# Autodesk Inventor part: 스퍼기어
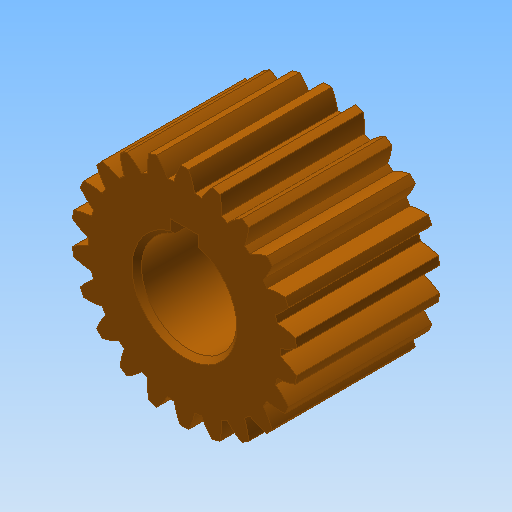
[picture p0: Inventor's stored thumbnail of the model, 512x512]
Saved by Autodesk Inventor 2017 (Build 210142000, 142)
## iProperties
Created: 2019-03
Part Number: 스퍼기어
Material: 강철
Document SubType Name: Modeling
Designer: mduedu
Categories: <?xml version="1.0" encoding="UTF-16"?> <MemberInstance><Categories><FamilyTemplate><FamilyTemplateParameter ValueType="xs:double" Id="1" ObjectReferenceKey="da
Density: 1 g/cm^3
Appearance: 주황색
CustomPartVersion: 1
Author: mduedu
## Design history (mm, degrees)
sketch "Sketch1"
  geometry: C1 r 23.6 at (0, 0)
  constraints: 1 centre point
  dimensions: "d0" = 47.2 diameter of C1 (= da_da)
extrude "Extrusion1" new body sketch "Sketch1" distance "d1" = 30 (= da_b); taper "d2" = 0 deg
workplane "Work Plane2"
sketch "Sketch2"
  geometry: C1 r 23.6 at (0, 0) reference; C2 r 22 at (0, 0)
  constraints: 1 centre point, 1 coincident
  dimensions: "d3" = 44 diameter of C2 (= da_dw)
feature "피치 지름" sketch "Sketch2" dims "d4" = 10, "d5" = 0
workplane "Work Plane8"
workplane "Work Plane9"
feature "스퍼 기어" dims "da_b" = 30, "da_d" = 44, "da_aw" = 44, "da_da" = 47.2, "da_df" = 40.172, "da_dw" = 44, angle "da_beta" = 0 deg, "da_lefttooth" = 0, "da_righttooth" = 0
sketch "스케치3"
  geometry: L1 (-3, 9.539)-(3, 9.539); L2 (3, 9.539)-(3, 12.8); L3 (3, 12.8)-(-3, 12.8); L4 (-3, 12.8)-(-3, 9.539); A1 r 10 centre (0, 0) between (-3, 9.539) and (3, 9.539); 1 further point
  constraints: 8 end point, 2 parallel, 2 point on circle, 1 centre point, 1 coincident, 1 horizontal, 1 perpendicular
  dimensions: "d49" = 20 diameter of A1; "d50" = 6 distance of L2.end L3.end; "d51" = 22.8 dimension on A1 L3
extrude "돌출2" cut sketch "스케치3" stored distance "d52" = 10; taper "d53" = 0 deg
chamfer "모따기1" distance "d54" = 1; stored, may be unused: second distance "d55" = 2, angle "d56" = 45 deg
body "Solid1"
body "Srf1"
other parameters: "d16" = 44 (= da_aw), "d17" = 0, "d34" = 1.428 (computed from da_z), "d39" = 0, "d41" = 0, "d43" = 44 (= da_aw), "d46" = 44 (= da_aw), "d47" = 0, "d48" = 0
